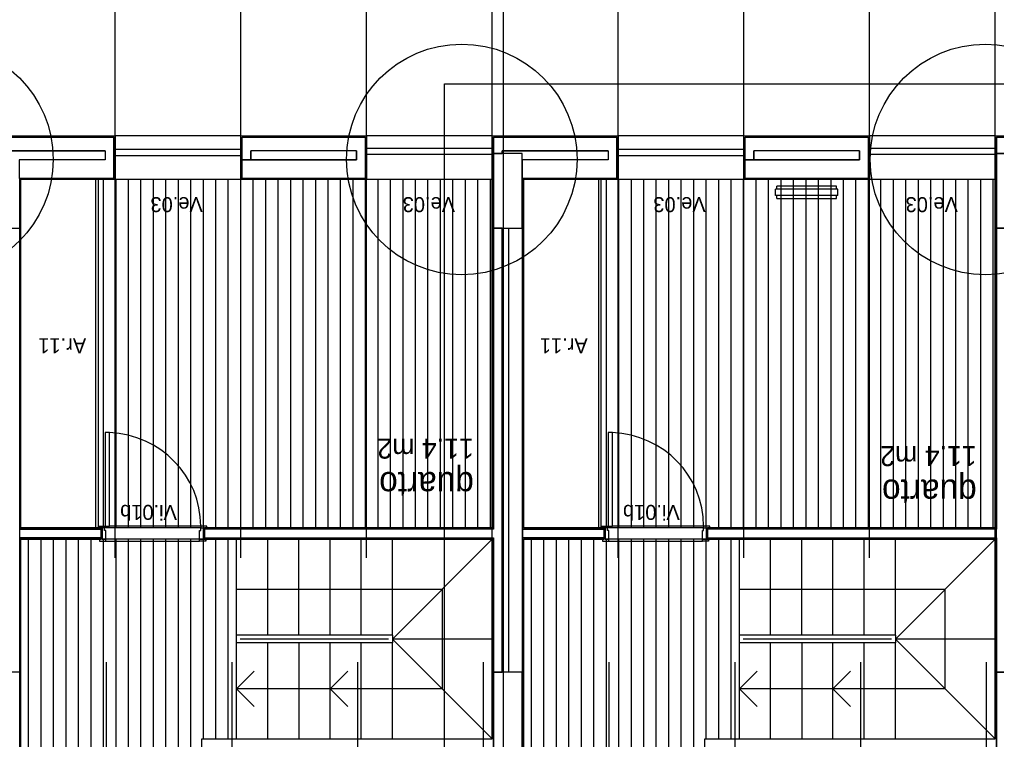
# Model space of a CAD drawing. Extents: x 1278 to 1356, y -253.7 to -224.
# Drawn here: x 1303.56 to 1311.39, y -236.76 to -230.99 of the extents above; entities that cross this region are included whole.
import ezdxf

# ---------------------------------------------------------------- set-up
doc = ezdxf.new("R2010")
doc.units = 0
for name, color, linetype in [('Level 1', 7, 'Continuous'), ('Level 10', 7, 'Continuous'), ('Level 13', 7, 'Continuous'), ('Level 2', 7, 'Continuous'), ('Level 4', 7, 'Continuous'), ('Level 40', 7, 'Continuous'), ('Level 59', 7, 'Continuous'), ('Level 60', 7, 'Continuous'), ('Level 65', 7, 'Continuous'), ('Level 66', 7, 'Continuous'), ('Level 67', 7, 'Continuous'), ('Level 69', 7, 'Continuous'), ('Level 70', 7, 'Continuous'), ('Level 93', 7, 'Continuous')]:
    doc.layers.add(name, color=color, linetype=linetype)

msp = doc.modelspace()

# ---------------------------------------------------------------- linework, layer by layer
at = {"layer": 'Level 1'}
for p, q in [((1303.329, -231.934), (1304.3165, -231.934)), ((1304.3165, -231.934), (1304.3165, -232.264)), ((1305.344, -231.934), (1306.3315, -231.934)), ((1305.344, -232.264), (1305.344, -231.934)), ((1306.3315, -231.934), (1306.3315, -232.264)), ((1307.359, -231.934), (1308.3465, -231.934)), ((1308.3465, -231.934), (1308.3465, -232.264)), ((1309.374, -231.934), (1310.3615, -231.934)), ((1309.374, -232.264), (1309.374, -231.934)), ((1310.3615, -231.934), (1310.3615, -232.264)), ((1311.389, -231.934), (1312.3765, -231.934)), ((1304.2465, -232.044), (1304.2465, -232.1143)), ((1305.414, -232.1143), (1305.414, -232.044)), ((1306.2615, -232.044), (1306.2615, -232.1143)), ((1307.429, -232.0639), (1307.429, -232.044)), ((1308.2765, -232.044), (1308.2765, -232.1143)), ((1309.444, -232.1143), (1309.444, -232.044)), ((1310.2915, -232.044), (1310.2915, -232.1143)), ((1304.3165, -232.264), (1303.5619, -232.264)), ((1306.3315, -232.264), (1305.344, -232.264)), ((1308.3465, -232.264), (1307.5919, -232.264)), ((1310.3615, -232.264), (1309.374, -232.264)), ((1304.2127, -235.0752), (1303.5623, -235.0752)), ((1304.2127, -235.0652), (1304.2127, -235.1552)), ((1305.0427, -235.0652), (1305.0427, -235.0752)), ((1305.0427, -235.0652), (1305.0427, -235.1552)), ((1308.2423, -235.0752), (1307.5919, -235.0752)), ((1308.2423, -235.0652), (1308.2423, -235.1552)), ((1309.0723, -235.0652), (1309.0723, -235.0752)), ((1309.0723, -235.0652), (1309.0723, -235.1552)), ((1303.5623, -235.1452), (1304.2127, -235.1452)), ((1305.0427, -235.1452), (1305.0427, -235.1552)), ((1305.0427, -235.1452), (1307.359, -235.1452)), ((1307.5919, -235.1452), (1308.2423, -235.1452)), ((1309.0723, -235.1452), (1309.0723, -235.1552)), ((1309.0723, -235.1452), (1311.389, -235.1452))]:
    msp.add_line(p, q, dxfattribs=at)
for points in [[(1307.359, -235.0752), (1305.0427, -235.0752)], [(1311.389, -235.0752), (1309.0723, -235.0752)]]:
    msp.add_lwpolyline(points, dxfattribs=at)
at = {"layer": 'Level 10'}
for p, q in [((1304.2337, -235.0652), (1304.2337, -232.274)), ((1304.3337, -235.0652), (1304.3337, -232.274)), ((1304.4337, -235.0652), (1304.4337, -232.274)), ((1304.5337, -235.0652), (1304.5337, -232.274)), ((1304.6337, -235.0652), (1304.6337, -232.274)), ((1304.7337, -235.0652), (1304.7337, -232.274)), ((1304.8337, -235.0652), (1304.8337, -232.274)), ((1304.9337, -235.0652), (1304.9337, -232.274)), ((1305.0337, -235.0652), (1305.0337, -232.274)), ((1305.1337, -235.0652), (1305.1337, -232.274)), ((1305.2337, -235.0652), (1305.2337, -232.274)), ((1305.3337, -235.0652), (1305.3337, -232.274)), ((1305.4337, -235.0652), (1305.4337, -232.274)), ((1305.5337, -235.0652), (1305.5337, -232.274)), ((1305.6337, -235.0652), (1305.6337, -232.274)), ((1305.7337, -235.0652), (1305.7337, -232.274)), ((1305.8337, -235.0652), (1305.8337, -232.274)), ((1305.9337, -235.0652), (1305.9337, -232.274)), ((1306.0337, -235.0652), (1306.0337, -232.274)), ((1306.1337, -235.0652), (1306.1337, -232.274)), ((1306.2337, -235.0652), (1306.2337, -232.274)), ((1306.3337, -235.0652), (1306.3337, -232.274)), ((1306.4337, -235.0652), (1306.4337, -232.274)), ((1306.5337, -235.0652), (1306.5337, -232.274)), ((1306.6337, -235.0652), (1306.6337, -232.274)), ((1306.7337, -235.0652), (1306.7337, -232.274)), ((1306.8337, -235.0652), (1306.8337, -232.274)), ((1306.9337, -235.0652), (1306.9337, -232.274)), ((1307.0337, -235.0652), (1307.0337, -232.274)), ((1307.1337, -235.0652), (1307.1337, -232.274)), ((1307.2337, -235.0652), (1307.2337, -232.274)), ((1307.3337, -235.0652), (1307.3337, -232.274)), ((1308.2633, -235.0652), (1308.2633, -232.274)), ((1308.3633, -235.0652), (1308.3633, -232.274)), ((1308.4633, -235.0652), (1308.4633, -232.274)), ((1308.5633, -235.0652), (1308.5633, -232.274)), ((1308.6633, -235.0652), (1308.6633, -232.274)), ((1308.7633, -235.0652), (1308.7633, -232.274)), ((1308.8633, -235.0652), (1308.8633, -232.274)), ((1308.9633, -235.0652), (1308.9633, -232.274)), ((1309.0633, -235.0652), (1309.0633, -232.274)), ((1309.1633, -235.0652), (1309.1633, -232.274)), ((1309.2633, -235.0652), (1309.2633, -232.274)), ((1309.3633, -235.0652), (1309.3633, -232.274)), ((1309.4633, -235.0652), (1309.4633, -232.274)), ((1309.5633, -235.0652), (1309.5633, -232.274)), ((1309.6633, -235.0652), (1309.6633, -232.274)), ((1309.7633, -235.0652), (1309.7633, -232.274)), ((1309.8633, -235.0652), (1309.8633, -232.274)), ((1309.9633, -235.0652), (1309.9633, -232.274)), ((1310.0633, -235.0652), (1310.0633, -232.274)), ((1310.1633, -235.0652), (1310.1633, -232.274)), ((1310.2633, -235.0652), (1310.2633, -232.274)), ((1310.3633, -235.0652), (1310.3633, -232.274)), ((1310.4633, -235.0652), (1310.4633, -232.274)), ((1310.5633, -235.0652), (1310.5633, -232.274)), ((1310.6633, -235.0652), (1310.6633, -232.274)), ((1310.7633, -235.0652), (1310.7633, -232.274)), ((1310.8633, -235.0652), (1310.8633, -232.274)), ((1310.9633, -235.0652), (1310.9633, -232.274)), ((1311.0633, -235.0652), (1311.0633, -232.274)), ((1311.1633, -235.0652), (1311.1633, -232.274)), ((1311.2633, -235.0652), (1311.2633, -232.274)), ((1311.3633, -235.0652), (1311.3633, -232.274)), ((1305.0127, -235.0652), (1304.2427, -235.0652)), ((1309.0423, -235.0652), (1308.2723, -235.0652)), ((1303.6337, -243.574), (1303.6337, -235.1552)), ((1303.7337, -243.574), (1303.7337, -235.1552)), ((1303.8337, -243.574), (1303.8337, -235.1552)), ((1303.9337, -243.574), (1303.9337, -235.1552)), ((1304.0337, -243.574), (1304.0337, -235.1552)), ((1304.1337, -243.574), (1304.1337, -235.1552)), ((1304.2337, -243.574), (1304.2337, -235.1552)), ((1305.0027, -235.1552), (1304.2527, -235.1552)), ((1304.3337, -243.574), (1304.3337, -235.1552)), ((1304.4337, -243.574), (1304.4337, -235.1552)), ((1304.5337, -243.574), (1304.5337, -235.1552)), ((1304.6337, -243.574), (1304.6337, -235.1552)), ((1304.7337, -243.574), (1304.7337, -235.1552)), ((1304.8337, -243.574), (1304.8337, -235.1552)), ((1304.9337, -243.574), (1304.9337, -235.1552)), ((1305.0337, -236.7552), (1305.0337, -235.1552)), ((1305.1337, -236.7552), (1305.1337, -235.1552)), ((1305.2337, -236.7552), (1305.2337, -235.1552)), ((1307.6633, -243.574), (1307.6633, -235.1552)), ((1307.7633, -243.574), (1307.7633, -235.1552)), ((1307.8633, -243.574), (1307.8633, -235.1552)), ((1307.9633, -243.574), (1307.9633, -235.1552)), ((1308.0633, -243.574), (1308.0633, -235.1552)), ((1308.1633, -243.574), (1308.1633, -235.1552)), ((1308.2633, -243.574), (1308.2633, -235.1552)), ((1309.0323, -235.1552), (1308.2823, -235.1552)), ((1308.3633, -243.574), (1308.3633, -235.1552)), ((1308.4633, -243.574), (1308.4633, -235.1552)), ((1308.5633, -243.574), (1308.5633, -235.1552)), ((1308.6633, -243.574), (1308.6633, -235.1552)), ((1308.7633, -243.574), (1308.7633, -235.1552)), ((1308.8633, -243.574), (1308.8633, -235.1552)), ((1308.9633, -243.574), (1308.9633, -235.1552)), ((1309.0633, -236.7552), (1309.0633, -235.1552)), ((1309.1633, -236.7552), (1309.1633, -235.1552)), ((1309.2633, -236.7552), (1309.2633, -235.1552))]:
    msp.add_line(p, q, dxfattribs=at)
at = {"layer": 'Level 13'}
for p, q in [((1304.1727, -235.0652), (1304.1727, -232.274)), ((1304.1927, -235.0652), (1304.1927, -232.274)), ((1308.2023, -235.0652), (1308.2023, -232.274)), ((1308.2223, -235.0652), (1308.2223, -232.274)), ((1304.2477, -234.3002), (1304.2477, -235.0502)), ((1304.2827, -234.3002), (1304.2477, -234.3002)), ((1304.2827, -235.0502), (1304.2827, -234.3002)), ((1308.2773, -234.3002), (1308.2773, -235.0502)), ((1308.3123, -234.3002), (1308.2773, -234.3002)), ((1308.3123, -235.0502), (1308.3123, -234.3002)), ((1304.1927, -235.0502), (1304.2427, -235.0502)), ((1304.1927, -235.0602), (1304.1927, -235.0502)), ((1304.1977, -235.0602), (1304.1927, -235.0602)), ((1304.1977, -235.0652), (1304.1977, -235.0602)), ((1304.2427, -235.0652), (1304.1977, -235.0652)), ((1304.2227, -235.0652), (1304.2227, -235.1552)), ((1304.2427, -235.0652), (1304.2227, -235.0652)), ((1304.2427, -235.0502), (1304.2427, -235.0652)), ((1304.2427, -235.0852), (1304.2427, -235.0652)), ((1304.2527, -235.0852), (1304.2427, -235.0852)), ((1304.2477, -235.0502), (1304.2827, -235.0502)), ((1304.2527, -235.1552), (1304.2527, -235.0852)), ((1305.0027, -235.1552), (1305.0027, -235.0852)), ((1305.0027, -235.0852), (1305.0127, -235.0852)), ((1305.0627, -235.0502), (1305.0127, -235.0502)), ((1305.0127, -235.0502), (1305.0127, -235.0652)), ((1305.0127, -235.0852), (1305.0127, -235.0652)), ((1305.0127, -235.0652), (1305.0327, -235.0652)), ((1305.0127, -235.0652), (1305.0577, -235.0652)), ((1305.0327, -235.0652), (1305.0327, -235.1552)), ((1305.0577, -235.0652), (1305.0577, -235.0602)), ((1305.0577, -235.0602), (1305.0627, -235.0602)), ((1305.0627, -235.0602), (1305.0627, -235.0502)), ((1308.2223, -235.0502), (1308.2723, -235.0502)), ((1308.2223, -235.0602), (1308.2223, -235.0502)), ((1308.2273, -235.0602), (1308.2223, -235.0602)), ((1308.2273, -235.0652), (1308.2273, -235.0602)), ((1308.2723, -235.0652), (1308.2273, -235.0652)), ((1308.2523, -235.0652), (1308.2523, -235.1552)), ((1308.2723, -235.0652), (1308.2523, -235.0652)), ((1308.2723, -235.0502), (1308.2723, -235.0652)), ((1308.2723, -235.0852), (1308.2723, -235.0652)), ((1308.2823, -235.0852), (1308.2723, -235.0852)), ((1308.2773, -235.0502), (1308.3123, -235.0502)), ((1308.2823, -235.1552), (1308.2823, -235.0852)), ((1309.0323, -235.1552), (1309.0323, -235.0852)), ((1309.0323, -235.0852), (1309.0423, -235.0852)), ((1309.0923, -235.0502), (1309.0423, -235.0502)), ((1309.0423, -235.0502), (1309.0423, -235.0652)), ((1309.0423, -235.0852), (1309.0423, -235.0652)), ((1309.0423, -235.0652), (1309.0623, -235.0652)), ((1309.0423, -235.0652), (1309.0873, -235.0652)), ((1309.0623, -235.0652), (1309.0623, -235.1552)), ((1309.0873, -235.0652), (1309.0873, -235.0602)), ((1309.0873, -235.0602), (1309.0923, -235.0602)), ((1309.0923, -235.0602), (1309.0923, -235.0502)), ((1304.2077, -235.1602), (1304.2027, -235.1602)), ((1304.2027, -235.1602), (1304.2027, -235.1702)), ((1304.2527, -235.1552), (1304.2077, -235.1552)), ((1304.2077, -235.1552), (1304.2077, -235.1602)), ((1304.2227, -235.1552), (1304.2527, -235.1552)), ((1304.2527, -235.1702), (1304.2527, -235.1552)), ((1305.0327, -235.1552), (1305.0027, -235.1552)), ((1305.0027, -235.1702), (1305.0027, -235.1552)), ((1305.0027, -235.1552), (1305.0477, -235.1552)), ((1305.0477, -235.1552), (1305.0477, -235.1602)), ((1305.0477, -235.1602), (1305.0527, -235.1602)), ((1305.0527, -235.1602), (1305.0527, -235.1702)), ((1308.2373, -235.1602), (1308.2323, -235.1602)), ((1308.2323, -235.1602), (1308.2323, -235.1702)), ((1308.2823, -235.1552), (1308.2373, -235.1552)), ((1308.2373, -235.1552), (1308.2373, -235.1602)), ((1308.2523, -235.1552), (1308.2823, -235.1552)), ((1308.2823, -235.1702), (1308.2823, -235.1552)), ((1309.0623, -235.1552), (1309.0323, -235.1552)), ((1309.0323, -235.1702), (1309.0323, -235.1552)), ((1309.0323, -235.1552), (1309.0773, -235.1552)), ((1309.0773, -235.1552), (1309.0773, -235.1602)), ((1309.0773, -235.1602), (1309.0823, -235.1602)), ((1309.0823, -235.1602), (1309.0823, -235.1702)), ((1304.2027, -235.1702), (1304.2527, -235.1702)), ((1305.0527, -235.1702), (1305.0027, -235.1702)), ((1308.2323, -235.1702), (1308.2823, -235.1702)), ((1309.0823, -235.1702), (1309.0323, -235.1702))]:
    msp.add_line(p, q, dxfattribs=at)
at = {"layer": 'Level 2'}
for p, q in [((1305.334, -231.924), (1304.3265, -231.924)), ((1307.349, -231.924), (1306.3415, -231.924)), ((1309.364, -231.924), (1308.3565, -231.924)), ((1311.379, -231.924), (1310.3715, -231.924)), ((1307.349, -232.024), (1306.3415, -232.024)), ((1311.379, -232.024), (1310.3715, -232.024)), ((1305.334, -232.034), (1304.3265, -232.034)), ((1305.334, -232.084), (1304.3265, -232.084)), ((1307.349, -232.074), (1306.3415, -232.074)), ((1309.364, -232.034), (1308.3565, -232.034)), ((1309.364, -232.084), (1308.3565, -232.084)), ((1311.379, -232.074), (1310.3715, -232.074)), ((1305.334, -232.274), (1304.3265, -232.274)), ((1307.349, -232.274), (1306.3415, -232.274)), ((1309.364, -232.274), (1308.3565, -232.274)), ((1311.379, -232.274), (1310.3715, -232.274)), ((1305.299, -235.9252), (1305.299, -235.1552)), ((1305.549, -235.9252), (1305.549, -235.1552)), ((1305.799, -235.9252), (1305.799, -235.1552)), ((1306.049, -235.9252), (1306.049, -235.1552)), ((1306.299, -235.9252), (1306.299, -235.1552)), ((1306.549, -235.9252), (1306.549, -235.1552)), ((1306.549, -235.9552), (1307.349, -235.1552)), ((1309.329, -235.9252), (1309.329, -235.1552)), ((1309.579, -235.9252), (1309.579, -235.1552)), ((1309.829, -235.9252), (1309.829, -235.1552)), ((1310.079, -235.9252), (1310.079, -235.1552)), ((1310.329, -235.9252), (1310.329, -235.1552)), ((1310.579, -235.9252), (1310.579, -235.1552)), ((1310.579, -235.9552), (1311.379, -235.1552)), ((1305.299, -235.5552), (1306.949, -235.5552)), ((1306.949, -236.3552), (1306.949, -235.5552)), ((1309.329, -235.5552), (1310.979, -235.5552)), ((1310.979, -236.3552), (1310.979, -235.5552)), ((1306.549, -235.9252), (1305.299, -235.9252)), ((1305.299, -235.9852), (1305.299, -235.9252)), ((1306.549, -235.9252), (1306.549, -235.9852)), ((1310.579, -235.9252), (1309.329, -235.9252)), ((1309.329, -235.9852), (1309.329, -235.9252)), ((1310.579, -235.9252), (1310.579, -235.9852)), ((1305.299, -236.7552), (1305.299, -235.9852)), ((1306.549, -235.9852), (1305.299, -235.9852)), ((1306.5171, -235.9552), (1305.3281, -235.9552)), ((1305.549, -236.7552), (1305.549, -235.9852)), ((1305.799, -235.9852), (1305.799, -236.7552)), ((1306.049, -236.7552), (1306.049, -235.9852)), ((1306.299, -236.7552), (1306.299, -235.9852)), ((1307.349, -235.9552), (1306.549, -235.9552)), ((1306.549, -235.9552), (1307.349, -236.7552)), ((1306.549, -236.7552), (1306.549, -235.9852)), ((1309.329, -236.7552), (1309.329, -235.9852)), ((1310.579, -235.9852), (1309.329, -235.9852)), ((1310.5471, -235.9552), (1309.3581, -235.9552)), ((1309.579, -236.7552), (1309.579, -235.9852)), ((1309.829, -235.9852), (1309.829, -236.7552)), ((1310.079, -236.7552), (1310.079, -235.9852)), ((1310.329, -236.7552), (1310.329, -235.9852)), ((1311.379, -235.9552), (1310.579, -235.9552)), ((1310.579, -235.9552), (1311.379, -236.7552)), ((1310.579, -236.7552), (1310.579, -235.9852)), ((1305.4404, -236.2137), (1305.299, -236.3552)), ((1306.1904, -236.2137), (1306.049, -236.3552)), ((1309.4704, -236.2137), (1309.329, -236.3552)), ((1310.2204, -236.2137), (1310.079, -236.3552)), ((1305.4404, -236.4966), (1305.299, -236.3552)), ((1306.049, -236.3552), (1305.299, -236.3552)), ((1306.949, -236.3552), (1306.049, -236.3552)), ((1306.1904, -236.4966), (1306.049, -236.3552)), ((1309.4704, -236.4966), (1309.329, -236.3552)), ((1310.079, -236.3552), (1309.329, -236.3552)), ((1310.979, -236.3552), (1310.079, -236.3552)), ((1310.2204, -236.4966), (1310.079, -236.3552))]:
    msp.add_line(p, q, dxfattribs=at)
at = {"layer": 'Level 4'}
for p, q in [((1305.0127, -235.0502), (1304.2827, -235.0502)), ((1309.0423, -235.0502), (1308.3123, -235.0502)), ((1304.2527, -235.1702), (1305.0027, -235.1702)), ((1308.2823, -235.1702), (1309.0323, -235.1702))]:
    msp.add_line(p, q, dxfattribs=at)
for centre in [(1304.2495, -235.0502), (1308.2791, -235.0502)]:
    msp.add_ellipse(centre, major_axis=(-0.7632, 0), ratio=0.982661, start_param=3.141593, end_param=4.668897, dxfattribs=at)
at = {"layer": 'Level 59'}
msp.add_lwpolyline([(1312.108, -245.3846), (1306.9649, -245.3846), (1306.9649, -231.5072), (1312.108, -231.5072)], close=True, dxfattribs=at)
at = {"layer": 'Level 65'}
for p, q in [((1303.319, -231.924), (1304.3265, -231.924)), ((1304.3265, -231.924), (1304.3265, -232.274)), ((1305.334, -232.274), (1305.334, -231.924)), ((1305.334, -231.924), (1306.3415, -231.924)), ((1306.3415, -231.924), (1306.3415, -232.274)), ((1307.349, -231.924), (1308.3565, -231.924)), ((1308.3565, -231.924), (1308.3565, -232.274)), ((1309.364, -232.274), (1309.364, -231.924)), ((1309.364, -231.924), (1310.3715, -231.924)), ((1310.3715, -231.924), (1310.3715, -232.274)), ((1311.379, -231.924), (1312.3865, -231.924)), ((1311.379, -235.0652), (1311.379, -231.924)), ((1304.3265, -232.274), (1303.5719, -232.274)), ((1303.5723, -235.0652), (1303.5723, -232.274)), ((1303.5723, -235.0652), (1303.5723, -232.274)), ((1306.3415, -232.274), (1305.334, -232.274)), ((1307.349, -235.0652), (1307.349, -232.274)), ((1307.6019, -235.0652), (1307.6019, -232.274)), ((1307.6019, -235.0652), (1307.6019, -232.274)), ((1308.3565, -232.274), (1307.6019, -232.274)), ((1310.3715, -232.274), (1309.364, -232.274)), ((1304.2127, -235.0652), (1303.5723, -235.0652)), ((1308.2423, -235.0652), (1307.6019, -235.0652)), ((1303.5723, -235.1552), (1304.2127, -235.1552)), ((1303.5723, -243.574), (1303.5723, -235.1552)), ((1305.0427, -235.1552), (1307.349, -235.1552)), ((1307.349, -236.7552), (1307.349, -235.1552)), ((1307.6019, -235.1552), (1308.2423, -235.1552)), ((1307.6019, -243.574), (1307.6019, -235.1552)), ((1309.0723, -235.1552), (1311.379, -235.1552)), ((1311.379, -236.7552), (1311.379, -235.1552)), ((1305.0223, -236.7552), (1307.349, -236.7552)), ((1305.0223, -237.1748), (1305.0223, -236.7552)), ((1309.0519, -236.7552), (1311.379, -236.7552)), ((1309.0519, -237.1748), (1309.0519, -236.7552))]:
    msp.add_line(p, q, dxfattribs=at)
for points in [[(1307.349, -235.0652), (1305.0427, -235.0652)], [(1311.379, -235.0652), (1309.0723, -235.0652)]]:
    msp.add_lwpolyline(points, dxfattribs=at)
at = {"layer": 'Level 66'}
for p, q in [((1307.359, -235.0752), (1307.359, -231.934)), ((1311.389, -237.0363), (1311.389, -231.934)), ((1304.2465, -232.044), (1303.399, -232.044)), ((1306.2615, -232.044), (1305.414, -232.044)), ((1308.2765, -232.044), (1307.429, -232.044)), ((1310.2915, -232.044), (1309.444, -232.044)), ((1304.2465, -232.1143), (1303.559, -232.1143)), ((1306.2615, -232.1143), (1305.414, -232.1143)), ((1308.2765, -232.1143), (1307.589, -232.1143)), ((1310.2915, -232.1143), (1309.444, -232.1143)), ((1303.5623, -243.584), (1303.5623, -232.264)), ((1303.5623, -243.584), (1303.5623, -232.264)), ((1303.5623, -243.584), (1303.5623, -232.264)), ((1307.5919, -243.584), (1307.5919, -232.264)), ((1307.5919, -243.584), (1307.5919, -232.264)), ((1307.5919, -243.584), (1307.5919, -232.264)), ((1310.1078, -232.3257), (1309.6278, -232.3257)), ((1309.6278, -232.3507), (1309.6278, -232.3257)), ((1310.1078, -232.3507), (1310.1078, -232.3257)), ((1310.1178, -232.3507), (1309.6178, -232.3507)), ((1309.6178, -232.4007), (1309.6178, -232.3507)), ((1310.1178, -232.4007), (1309.6178, -232.4007)), ((1309.6278, -232.4257), (1309.6278, -232.4007)), ((1310.1078, -232.4257), (1310.1078, -232.4007)), ((1310.1178, -232.4007), (1310.1178, -232.3507)), ((1309.6278, -232.4257), (1310.1078, -232.4257)), ((1307.4294, -236.2213), (1307.4294, -232.6639)), ((1307.4819, -236.2213), (1307.4819, -232.6639)), ((1307.3594, -237.0363), (1307.3594, -235.1452))]:
    msp.add_line(p, q, dxfattribs=at)
for points in [[(1307.359, -232.6639), (1307.589, -232.6639), (1307.589, -232.0639), (1307.359, -232.0639)], [(1307.359, -232.6639), (1307.589, -232.6639), (1307.589, -232.0639), (1307.359, -232.0639)], [(1311.389, -232.6639), (1311.619, -232.6639), (1311.619, -232.0639), (1311.389, -232.0639)], [(1311.389, -232.6639), (1311.619, -232.6639), (1311.619, -232.0639), (1311.389, -232.0639)], [(1307.359, -236.9213), (1307.589, -236.9213), (1307.589, -236.2213), (1307.359, -236.2213)], [(1307.359, -236.9213), (1307.589, -236.9213), (1307.589, -236.2213), (1307.359, -236.2213)], [(1311.389, -236.9213), (1311.619, -236.9213), (1311.619, -236.2213), (1311.389, -236.2213)]]:
    msp.add_lwpolyline(points, close=True, dxfattribs=at)
at = {"layer": 'Level 67'}
for points in [[(1303.399, -232.044), (1304.2465, -232.044), (1304.2465, -232.1143), (1303.559, -232.1143), (1303.559, -232.264), (1304.3165, -232.264), (1304.3165, -231.934), (1303.329, -231.934), (1303.329, -232.0639), (1303.399, -232.0639)], [(1306.3315, -231.934), (1306.3315, -232.264), (1305.344, -232.264), (1305.344, -232.1143), (1306.2615, -232.1143), (1306.2615, -232.044), (1305.414, -232.044), (1305.414, -232.1143), (1305.344, -232.1143), (1305.344, -231.934)], [(1307.429, -232.044), (1308.2765, -232.044), (1308.2765, -232.1143), (1307.589, -232.1143), (1307.589, -232.264), (1308.3465, -232.264), (1308.3465, -231.934), (1307.359, -231.934), (1307.359, -232.0639), (1307.429, -232.0639)], [(1310.3615, -231.934), (1310.3615, -232.264), (1309.374, -232.264), (1309.374, -232.1143), (1310.2915, -232.1143), (1310.2915, -232.044), (1309.444, -232.044), (1309.444, -232.1143), (1309.374, -232.1143), (1309.374, -231.934)], [(1311.459, -232.044), (1312.3065, -232.044), (1312.3065, -232.1143), (1311.619, -232.1143), (1311.619, -232.264), (1312.3765, -232.264), (1312.3765, -231.934), (1311.389, -231.934), (1311.389, -232.0639), (1311.459, -232.0639)], [(1304.2127, -235.0752), (1304.2127, -235.1452), (1303.5623, -235.1452), (1303.5623, -236.2213), (1303.4523, -236.2213), (1303.4523, -232.6639), (1303.5623, -232.6639), (1303.5623, -235.0752)], [(1307.4294, -232.6639), (1307.359, -232.6639), (1307.359, -235.0752), (1305.0427, -235.0752), (1305.0427, -235.1452), (1307.359, -235.1452), (1307.359, -236.2213), (1307.4294, -236.2213), (1307.4294, -232.6639)], [(1307.5919, -236.2213), (1307.4819, -236.2213), (1307.4819, -232.6639), (1307.5919, -232.6639)], [(1311.459, -232.6639), (1311.389, -232.6639), (1311.389, -235.0752), (1309.0723, -235.0752), (1309.0723, -235.1452), (1311.389, -235.1452), (1311.389, -236.2213), (1311.459, -236.2213)], [(1308.2423, -235.0752), (1308.2423, -235.1452), (1307.5919, -235.1452), (1307.5919, -235.0752)]]:
    msp.add_lwpolyline(points, close=True, dxfattribs=at)
at = {"layer": 'Level 69'}
for centre in [(1302.9066, -232.1122), (1307.1044, -232.1122), (1311.3004, -232.1122)]:
    msp.add_circle(centre, 0.9238, dxfattribs=at)
at = {"layer": 'Level 70'}
msp.add_line((1307.439, -250.7923), (1307.439, -229.6198), dxfattribs=at)
at = {"layer": 'Level 93'}
for p, q in [((1304.3265, -235.3039), (1304.3265, -224.3117)), ((1305.334, -235.3039), (1305.334, -224.3117)), ((1306.3415, -235.3039), (1306.3415, -224.3117)), ((1307.349, -235.3039), (1307.349, -224.3117)), ((1308.3565, -235.3039), (1308.3565, -224.3117)), ((1309.364, -235.3039), (1309.364, -224.3117)), ((1310.3715, -235.3039), (1310.3715, -224.3117)), ((1311.379, -235.3039), (1311.379, -224.3117)), ((1304.2565, -246.757), (1304.2565, -236.1407)), ((1305.264, -246.757), (1305.264, -236.1407)), ((1306.2715, -246.757), (1306.2715, -236.1407)), ((1307.279, -246.757), (1307.279, -236.1407)), ((1308.2865, -246.757), (1308.2865, -236.1407)), ((1309.294, -246.757), (1309.294, -236.1407)), ((1310.3015, -246.757), (1310.3015, -236.1407)), ((1311.309, -246.757), (1311.309, -236.1407))]:
    msp.add_line(p, q, dxfattribs=at)

# ---------------------------------------------------------------- texts
at = {"layer": 'Level 40'}
for s, rotation, p in [('Ve.03', 180.00001, (1305.0293, -232.4145)), ('Ve.03', 180.00001, (1307.0506, -232.4145)), ('Ve.03', 180.00001, (1309.0589, -232.4145)), ('Ve.03', 180.00001, (1311.0802, -232.4145)), ('Ar.11', 179.99999, (1304.095, -233.5449)), ('Ar.11', 179.99999, (1308.1138, -233.5449)), ('Vi.01b', 180.00001, (1304.8219, -234.8804)), ('Vi.01b', 180.00001, (1308.8515, -234.8804))]:
    msp.add_text(s, height=0.12, rotation=rotation, dxfattribs=at).set_placement(p)
at = {"layer": 'Level 60'}
for s, height, p in [('11.4 m2', 0.16, (1307.201, -234.3497)), ('11.4 m2', 0.16, (1311.2306, -234.4097)), ('quarto', 0.2, (1307.201, -234.6175)), ('quarto', 0.2, (1311.2306, -234.6775))]:
    msp.add_text(s, height=height, rotation=180, dxfattribs=at).set_placement(p)

doc.saveas('drawing.dxf')
